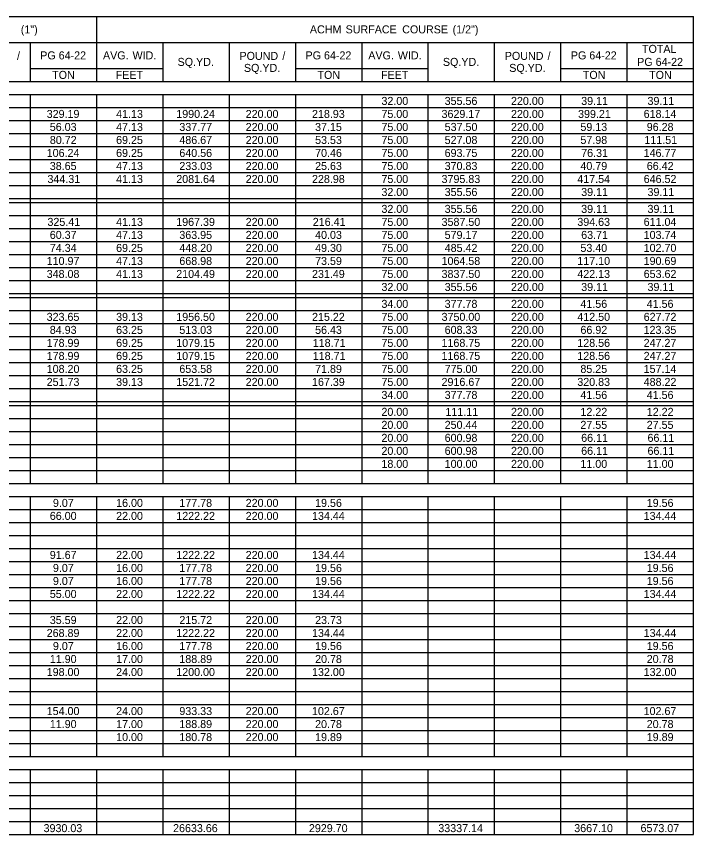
# Model space of a CAD drawing. Extents: x 977434 to 989596, y 1525697 to 1528336.
# Drawn here: x 983656.5 to 984062.7, y 1527610.4 to 1528101.1 of the extents above; entities that cross this region are included whole.
import ezdxf

# ---------------------------------------------------------------- set-up
doc = ezdxf.new("R2010")
doc.units = 0
doc.layers.add('Default', color=7, linetype='Continuous')

msp = doc.modelspace()

# ---------------------------------------------------------------- linework, layer by layer
at = {"layer": 'Default'}
for p, q in [((982704.74, 1528101.06), (984062.72, 1528101.06)), ((983704.7, 1528085.46), (983704.7, 1528101.06)), ((983704.7, 1528062.06), (983704.7, 1528101.06)), ((984062.72, 1527610.44), (984062.72, 1528101.06)), ((984062.72, 1527610.44), (984062.72, 1528101.06)), ((983028.44, 1528085.46), (984062.72, 1528085.46)), ((983664.92, 1528062.06), (983664.92, 1528085.46)), ((983744.48, 1528085.46), (983784.26, 1528085.46)), ((983744.48, 1528062.06), (983744.48, 1528085.46)), ((983784.26, 1528062.06), (983784.26, 1528085.46)), ((983824.04, 1528062.06), (983824.04, 1528085.46)), ((983863.82, 1528062.06), (983863.82, 1528085.46)), ((983903.6, 1528085.46), (983943.38, 1528085.46)), ((983903.6, 1528062.06), (983903.6, 1528085.46)), ((983943.38, 1528062.06), (983943.38, 1528085.46)), ((983983.16, 1528062.06), (983983.16, 1528085.46)), ((984022.94, 1528062.06), (984022.94, 1528085.46)), ((983664.92, 1528069.86), (983744.48, 1528069.86)), ((983704.7, 1528062.06), (983704.7, 1528069.86)), ((983744.48, 1528062.06), (983744.48, 1528069.86)), ((983824.04, 1528069.86), (983903.6, 1528069.86)), ((983863.82, 1528062.06), (983863.82, 1528069.86)), ((983903.6, 1528062.06), (983903.6, 1528069.86)), ((983983.16, 1528069.86), (984062.72, 1528069.86)), ((982704.74, 1528062.06), (984062.72, 1528062.06)), ((983585.36, 1528062.06), (983744.48, 1528062.06)), ((983744.48, 1528062.06), (983903.6, 1528062.06)), ((983903.6, 1528062.06), (984062.72, 1528062.06)), ((982704.74, 1528054.26), (984062.72, 1528054.26)), ((983664.92, 1527821.04), (983664.92, 1528054.26)), ((983664.92, 1527821.04), (983664.92, 1528054.26)), ((983704.7, 1527821.04), (983704.7, 1528054.26)), ((983704.7, 1527821.04), (983704.7, 1528054.26)), ((983744.48, 1527821.04), (983744.48, 1528054.26)), ((983744.48, 1527821.04), (983744.48, 1528054.26)), ((983784.26, 1527821.04), (983784.26, 1528054.26)), ((983784.26, 1527821.04), (983784.26, 1528054.26)), ((983824.04, 1527821.04), (983824.04, 1528054.26)), ((983824.04, 1527821.04), (983824.04, 1528054.26)), ((983863.82, 1527821.04), (983863.82, 1528054.26)), ((983863.82, 1527821.04), (983863.82, 1528054.26)), ((983903.6, 1527821.04), (983903.6, 1528054.26)), ((983903.6, 1527821.04), (983903.6, 1528054.26)), ((983943.38, 1527821.04), (983943.38, 1528054.26)), ((983943.38, 1527821.04), (983943.38, 1528054.26)), ((983983.16, 1527821.04), (983983.16, 1528054.26)), ((983983.16, 1527821.04), (983983.16, 1528054.26)), ((984022.94, 1527821.04), (984022.94, 1528054.26)), ((984022.94, 1527821.04), (984022.94, 1528054.26)), ((982704.74, 1528046.46), (984062.72, 1528046.46)), ((982704.74, 1528038.66), (984062.72, 1528038.66)), ((982704.74, 1528030.86), (984062.72, 1528030.86)), ((982704.74, 1528023.06), (984062.72, 1528023.06)), ((982704.74, 1528015.26), (984062.72, 1528015.26)), ((982704.74, 1528007.46), (984062.72, 1528007.46)), ((982704.74, 1527999.66), (984062.72, 1527999.66)), ((982704.74, 1527991.86), (984062.72, 1527991.86)), ((982704.74, 1527989.52), (984062.72, 1527989.52)), ((982704.74, 1527981.72), (984062.72, 1527981.72)), ((982704.74, 1527973.92), (984062.72, 1527973.92)), ((982704.74, 1527966.12), (984062.72, 1527966.12)), ((982704.74, 1527958.32), (984062.72, 1527958.32)), ((982704.74, 1527950.52), (984062.72, 1527950.52)), ((982704.74, 1527942.72), (984062.72, 1527942.72)), ((982704.74, 1527934.92), (984062.72, 1527934.92)), ((982704.74, 1527932.58), (984062.72, 1527932.58)), ((982704.74, 1527924.78), (984062.72, 1527924.78)), ((982704.74, 1527916.98), (984062.72, 1527916.98)), ((982704.74, 1527909.18), (984062.72, 1527909.18)), ((982704.74, 1527901.38), (984062.72, 1527901.38)), ((982704.74, 1527893.58), (984062.72, 1527893.58)), ((982704.74, 1527885.78), (984062.72, 1527885.78)), ((982704.74, 1527877.98), (984062.72, 1527877.98)), ((982704.74, 1527870.18), (984062.72, 1527870.18)), ((982704.74, 1527867.84), (984062.72, 1527867.84)), ((982704.74, 1527860.04), (984062.72, 1527860.04)), ((982704.74, 1527852.24), (984062.72, 1527852.24)), ((982704.74, 1527844.44), (984062.72, 1527844.44)), ((982704.74, 1527836.64), (984062.72, 1527836.64)), ((982704.74, 1527828.84), (984062.72, 1527828.84)), ((982704.74, 1527821.04), (984062.72, 1527821.04)), ((983386.46, 1527821.04), (983903.6, 1527821.04)), ((983903.6, 1527821.04), (983943.38, 1527821.04)), ((983943.38, 1527821.04), (984022.94, 1527821.04)), ((984022.94, 1527821.04), (984062.72, 1527821.04)), ((982704.74, 1527813.24), (984062.72, 1527813.24)), ((983664.92, 1527657.24), (983664.92, 1527813.24)), ((983664.92, 1527657.24), (983664.92, 1527813.24)), ((983704.7, 1527657.24), (983704.7, 1527813.24)), ((983704.7, 1527657.24), (983704.7, 1527813.24)), ((983744.48, 1527657.24), (983744.48, 1527813.24)), ((983744.48, 1527657.24), (983744.48, 1527813.24)), ((983784.26, 1527657.24), (983784.26, 1527813.24)), ((983784.26, 1527657.24), (983784.26, 1527813.24)), ((983824.04, 1527657.24), (983824.04, 1527813.24)), ((983824.04, 1527657.24), (983824.04, 1527813.24)), ((983863.82, 1527657.24), (983863.82, 1527813.24)), ((983863.82, 1527657.24), (983863.82, 1527813.24)), ((983903.6, 1527657.24), (983903.6, 1527813.24)), ((983903.6, 1527657.24), (983903.6, 1527813.24)), ((983943.38, 1527657.24), (983943.38, 1527813.24)), ((983943.38, 1527657.24), (983943.38, 1527813.24)), ((983983.16, 1527657.24), (983983.16, 1527813.24)), ((983983.16, 1527657.24), (983983.16, 1527813.24)), ((984022.94, 1527657.24), (984022.94, 1527813.24)), ((984022.94, 1527657.24), (984022.94, 1527813.24)), ((982704.74, 1527805.44), (984062.72, 1527805.44)), ((982704.74, 1527797.64), (984062.72, 1527797.64)), ((982704.74, 1527789.84), (984062.72, 1527789.84)), ((982704.74, 1527782.04), (984062.72, 1527782.04)), ((982704.74, 1527774.24), (984062.72, 1527774.24)), ((982704.74, 1527766.44), (984062.72, 1527766.44)), ((982704.74, 1527758.64), (984062.72, 1527758.64)), ((982704.74, 1527750.84), (984062.72, 1527750.84)), ((982704.74, 1527743.04), (984062.72, 1527743.04)), ((982704.74, 1527735.24), (984062.72, 1527735.24)), ((982704.74, 1527727.44), (984062.72, 1527727.44)), ((982704.74, 1527719.64), (984062.72, 1527719.64)), ((982704.74, 1527711.84), (984062.72, 1527711.84)), ((982704.74, 1527704.04), (984062.72, 1527704.04)), ((982704.74, 1527696.24), (984062.72, 1527696.24)), ((982704.74, 1527688.44), (984062.72, 1527688.44)), ((982704.74, 1527680.64), (984062.72, 1527680.64)), ((982704.74, 1527672.84), (984062.72, 1527672.84)), ((982704.74, 1527665.04), (984062.72, 1527665.04)), ((982704.74, 1527657.24), (984062.72, 1527657.24)), ((983346.68, 1527657.24), (983903.6, 1527657.24)), ((983903.6, 1527657.24), (983943.38, 1527657.24)), ((983943.38, 1527657.24), (984022.94, 1527657.24)), ((984022.94, 1527657.24), (984062.72, 1527657.24)), ((982704.74, 1527649.44), (984062.72, 1527649.44)), ((983664.92, 1527618.24), (983664.92, 1527649.44)), ((983664.92, 1527610.44), (983664.92, 1527649.44)), ((983704.7, 1527610.44), (983704.7, 1527649.44)), ((983704.7, 1527610.44), (983704.7, 1527649.44)), ((983744.48, 1527610.44), (983744.48, 1527649.44)), ((983744.48, 1527610.44), (983744.48, 1527649.44)), ((983784.26, 1527610.44), (983784.26, 1527649.44)), ((983784.26, 1527610.44), (983784.26, 1527649.44)), ((983824.04, 1527618.24), (983824.04, 1527649.44)), ((983824.04, 1527610.44), (983824.04, 1527649.44)), ((983863.82, 1527610.44), (983863.82, 1527649.44)), ((983863.82, 1527610.44), (983863.82, 1527649.44)), ((983903.6, 1527610.44), (983903.6, 1527649.44)), ((983903.6, 1527610.44), (983903.6, 1527649.44)), ((983943.38, 1527610.44), (983943.38, 1527649.44)), ((983943.38, 1527610.44), (983943.38, 1527649.44)), ((983983.16, 1527618.24), (983983.16, 1527649.44)), ((983983.16, 1527610.44), (983983.16, 1527649.44)), ((984022.94, 1527610.44), (984022.94, 1527649.44)), ((984022.94, 1527610.44), (984022.94, 1527649.44)), ((982704.74, 1527641.64), (984062.72, 1527641.64)), ((982704.74, 1527633.84), (984062.72, 1527633.84)), ((982704.74, 1527626.04), (984062.72, 1527626.04)), ((982704.74, 1527618.24), (984062.72, 1527618.24)), ((982704.74, 1527610.44), (984062.72, 1527610.44))]:
    msp.add_line(p, q, dxfattribs=at)

# ---------------------------------------------------------------- texts
for s, p in [(' (1")', (983657.4, 1528090.86)), ('ACHM', (983832.56, 1528090.86)), (' SURFACE', (983852.2, 1528090.86)), (' COURSE', (983886.15, 1528090.86)), (' (1/2")', (983916.38, 1528090.86)), ('TOTAL', (984031.75, 1528079.16)), (' /', (983655.11, 1528074.96)), ('PG', (983670.83, 1528075.26)), (' 64-22', (983680.12, 1528075.26)), ('AVG.', (983708.47, 1528075.26)), (' WID.', (983724.41, 1528075.26)), ('SQ.YD.', (983753.23, 1528071.36)), ('POUND', (983790.34, 1528074.96)), (' /', (983814.23, 1528074.96)), ('PG', (983829.95, 1528075.26)), (' 64-22', (983839.24, 1528075.26)), ('AVG.', (983867.59, 1528075.26)), (' WID.', (983883.53, 1528075.26)), ('SQ.YD.', (983912.35, 1528071.36)), ('POUND', (983949.46, 1528074.96)), (' /', (983973.35, 1528074.96)), ('PG', (983989.07, 1528075.26)), (' 64-22', (983998.36, 1528075.26)), ('PG', (984028.85, 1528071.36)), (' 64-22', (984038.14, 1528071.36)), ('SQ.YD.', (983793.01, 1528067.76)), ('SQ.YD.', (983952.13, 1528067.76)), ('TON', (983678, 1528063.56)), ('FEET', (983716.09, 1528063.56)), ('TON', (983837.12, 1528063.56)), ('FEET', (983875.21, 1528063.56)), ('TON', (983996.24, 1528063.56)), ('TON', (984036.02, 1528063.56)), ('32.00', (983875.48, 1528047.96)), ('355.56', (983913.39, 1528047.96)), ('220.00', (983953.18, 1528047.96)), ('39.11', (983995.28, 1528047.96)), ('39.11', (984035.06, 1528047.96)), ('329.19', (983674.71, 1528040.16)), ('41.13', (983716.35, 1528040.16)), ('1990.24', (983752.42, 1528040.16)), ('220.00', (983794.06, 1528040.16)), ('218.93', (983833.83, 1528040.16)), ('75.00', (983875.48, 1528040.16)), ('3629.17', (983911.53, 1528040.16)), ('220.00', (983953.18, 1528040.16)), ('399.21', (983993.41, 1528040.16)), ('618.14', (984032.74, 1528040.16)), ('56.03', (983676.57, 1528032.36)), ('47.13', (983716.35, 1528032.36)), ('337.77', (983754.27, 1528032.36)), ('220.00', (983794.06, 1528032.36)), ('37.15', (983835.68, 1528032.36)), ('75.00', (983875.48, 1528032.36)), ('537.50', (983913.4, 1528032.36)), ('220.00', (983953.18, 1528032.36)), ('59.13', (983994.81, 1528032.36)), ('96.28', (984034.59, 1528032.36)), ('80.72', (983676.6, 1528024.56)), ('69.25', (983716.34, 1528024.56)), ('486.67', (983754.27, 1528024.56)), ('220.00', (983794.06, 1528024.56)), ('53.53', (983835.69, 1528024.56)), ('75.00', (983875.48, 1528024.56)), ('527.08', (983913.39, 1528024.56)), ('220.00', (983953.18, 1528024.56)), ('57.98', (983994.81, 1528024.56)), ('111.51', (984033.19, 1528024.56)), ('106.24', (983674.72, 1528016.76)), ('69.25', (983716.34, 1528016.76)), ('640.56', (983754.27, 1528016.76)), ('220.00', (983794.06, 1528016.76)), ('70.46', (983835.69, 1528016.76)), ('75.00', (983875.48, 1528016.76)), ('693.75', (983913.37, 1528016.76)), ('220.00', (983953.18, 1528016.76)), ('76.31', (983995.28, 1528016.76)), ('146.77', (984032.73, 1528016.76)), ('38.65', (983676.56, 1528008.96)), ('47.13', (983716.35, 1528008.96)), ('233.03', (983754.27, 1528008.96)), ('220.00', (983794.06, 1528008.96)), ('25.63', (983835.69, 1528008.96)), ('75.00', (983875.48, 1528008.96)), ('370.83', (983913.39, 1528008.96)), ('220.00', (983953.18, 1528008.96)), ('40.79', (983994.81, 1528008.96)), ('66.42', (984034.62, 1528008.96)), ('344.31', (983675.17, 1528001.16)), ('41.13', (983716.35, 1528001.16)), ('2081.64', (983752.42, 1528001.16)), ('220.00', (983794.06, 1528001.16)), ('228.98', (983833.83, 1528001.16)), ('75.00', (983875.48, 1528001.16)), ('3795.83', (983911.53, 1528001.16)), ('220.00', (983953.18, 1528001.16)), ('417.54', (983992.96, 1528001.16)), ('646.52', (984032.76, 1528001.16)), ('32.00', (983875.48, 1527993.36)), ('355.56', (983913.39, 1527993.36)), ('220.00', (983953.18, 1527993.36)), ('39.11', (983995.28, 1527993.36)), ('39.11', (984035.06, 1527993.36)), ('32.00', (983875.48, 1527983.22)), ('355.56', (983913.39, 1527983.22)), ('220.00', (983953.18, 1527983.22)), ('39.11', (983995.28, 1527983.22)), ('39.11', (984035.06, 1527983.22)), ('325.41', (983675.17, 1527975.42)), ('41.13', (983716.35, 1527975.42)), ('1967.39', (983752.4, 1527975.42)), ('220.00', (983794.06, 1527975.42)), ('216.41', (983834.29, 1527975.42)), ('75.00', (983875.48, 1527975.42)), ('3587.50', (983911.54, 1527975.42)), ('220.00', (983953.18, 1527975.42)), ('394.63', (983992.95, 1527975.42)), ('611.04', (984032.74, 1527975.42)), ('60.37', (983676.57, 1527967.62)), ('47.13', (983716.35, 1527967.62)), ('363.95', (983754.25, 1527967.62)), ('220.00', (983794.06, 1527967.62)), ('40.03', (983835.69, 1527967.62)), ('75.00', (983875.48, 1527967.62)), ('579.17', (983913.39, 1527967.62)), ('220.00', (983953.18, 1527967.62)), ('63.71', (983995.28, 1527967.62)), ('103.74', (984032.74, 1527967.62)), ('74.34', (983676.59, 1527959.82)), ('69.25', (983716.34, 1527959.82)), ('448.20', (983754.28, 1527959.82)), ('220.00', (983794.06, 1527959.82)), ('49.30', (983835.7, 1527959.82)), ('75.00', (983875.48, 1527959.82)), ('485.42', (983913.42, 1527959.82)), ('220.00', (983953.18, 1527959.82)), ('53.40', (983994.82, 1527959.82)), ('102.70', (984032.74, 1527959.82)), ('110.97', (983674.71, 1527952.02)), ('47.13', (983716.35, 1527952.02)), ('668.98', (983754.27, 1527952.02)), ('220.00', (983794.06, 1527952.02)), ('73.59', (983835.69, 1527952.02)), ('75.00', (983875.48, 1527952.02)), ('1064.58', (983911.52, 1527952.02)), ('220.00', (983953.18, 1527952.02)), ('117.10', (983992.96, 1527952.02)), ('190.69', (984032.73, 1527952.02)), ('348.08', (983674.71, 1527944.22)), ('41.13', (983716.35, 1527944.22)), ('2104.49', (983752.4, 1527944.22)), ('220.00', (983794.06, 1527944.22)), ('231.49', (983833.83, 1527944.22)), ('75.00', (983875.48, 1527944.22)), ('3837.50', (983911.54, 1527944.22)), ('220.00', (983953.18, 1527944.22)), ('422.13', (983992.95, 1527944.22)), ('653.62', (984032.76, 1527944.22)), ('32.00', (983875.48, 1527936.42)), ('355.56', (983913.39, 1527936.42)), ('220.00', (983953.18, 1527936.42)), ('39.11', (983995.28, 1527936.42)), ('39.11', (984035.06, 1527936.42)), ('34.00', (983875.48, 1527926.28)), ('377.78', (983913.39, 1527926.28)), ('220.00', (983953.18, 1527926.28)), ('41.56', (983994.81, 1527926.28)), ('41.56', (984034.59, 1527926.28)), ('323.65', (983674.69, 1527918.48)), ('39.13', (983716.35, 1527918.48)), ('1956.50', (983752.42, 1527918.48)), ('220.00', (983794.06, 1527918.48)), ('215.22', (983833.86, 1527918.48)), ('75.00', (983875.48, 1527918.48)), ('3750.00', (983911.54, 1527918.48)), ('220.00', (983953.18, 1527918.48)), ('412.50', (983992.96, 1527918.48)), ('627.72', (984032.76, 1527918.48)), ('84.93', (983676.57, 1527910.68)), ('63.25', (983716.34, 1527910.68)), ('513.03', (983754.27, 1527910.68)), ('220.00', (983794.06, 1527910.68)), ('56.43', (983835.69, 1527910.68)), ('75.00', (983875.48, 1527910.68)), ('608.33', (983913.39, 1527910.68)), ('220.00', (983953.18, 1527910.68)), ('66.92', (983994.84, 1527910.68)), ('123.35', (984032.71, 1527910.68)), ('178.99', (983674.71, 1527902.88)), ('69.25', (983716.34, 1527902.88)), ('1079.15', (983752.39, 1527902.88)), ('220.00', (983794.06, 1527902.88)), ('118.71', (983834.29, 1527902.88)), ('75.00', (983875.48, 1527902.88)), ('1168.75', (983911.51, 1527902.88)), ('220.00', (983953.18, 1527902.88)), ('128.56', (983992.95, 1527902.88)), ('247.27', (984032.73, 1527902.88)), ('178.99', (983674.71, 1527895.08)), ('69.25', (983716.34, 1527895.08)), ('1079.15', (983752.39, 1527895.08)), ('220.00', (983794.06, 1527895.08)), ('118.71', (983834.29, 1527895.08)), ('75.00', (983875.48, 1527895.08)), ('1168.75', (983911.51, 1527895.08)), ('220.00', (983953.18, 1527895.08)), ('128.56', (983992.95, 1527895.08)), ('247.27', (984032.73, 1527895.08)), ('108.20', (983674.72, 1527887.28)), ('63.25', (983716.34, 1527887.28)), ('653.58', (983754.27, 1527887.28)), ('220.00', (983794.06, 1527887.28)), ('71.89', (983835.69, 1527887.28)), ('75.00', (983875.48, 1527887.28)), ('775.00', (983913.4, 1527887.28)), ('220.00', (983953.18, 1527887.28)), ('85.25', (983994.8, 1527887.28)), ('157.14', (984032.74, 1527887.28)), ('251.73', (983674.71, 1527879.48)), ('39.13', (983716.35, 1527879.48)), ('1521.72', (983752.43, 1527879.48)), ('220.00', (983794.06, 1527879.48)), ('167.39', (983833.83, 1527879.48)), ('75.00', (983875.48, 1527879.48)), ('2916.67', (983911.53, 1527879.48)), ('220.00', (983953.18, 1527879.48)), ('320.83', (983992.95, 1527879.48)), ('488.22', (984032.76, 1527879.48)), ('34.00', (983875.48, 1527871.68)), ('377.78', (983913.39, 1527871.68)), ('220.00', (983953.18, 1527871.68)), ('41.56', (983994.81, 1527871.68)), ('41.56', (984034.59, 1527871.68)), ('20.00', (983875.48, 1527861.54)), ('111.11', (983913.85, 1527861.54)), ('220.00', (983953.18, 1527861.54)), ('12.22', (983994.84, 1527861.54)), ('12.22', (984034.62, 1527861.54)), ('20.00', (983875.48, 1527853.74)), ('250.44', (983913.4, 1527853.74)), ('220.00', (983953.18, 1527853.74)), ('27.55', (983994.8, 1527853.74)), ('27.55', (984034.58, 1527853.74)), ('20.00', (983875.48, 1527845.94)), ('600.98', (983913.39, 1527845.94)), ('220.00', (983953.18, 1527845.94)), ('66.11', (983995.28, 1527845.94)), ('66.11', (984035.06, 1527845.94)), ('20.00', (983875.48, 1527838.14)), ('600.98', (983913.39, 1527838.14)), ('220.00', (983953.18, 1527838.14)), ('66.11', (983995.28, 1527838.14)), ('66.11', (984035.06, 1527838.14)), ('18.00', (983875.48, 1527830.34)), ('100.00', (983913.4, 1527830.34)), ('220.00', (983953.18, 1527830.34)), ('11.00', (983994.82, 1527830.34)), ('11.00', (984034.6, 1527830.34)), ('9.07', (983678.44, 1527806.94)), ('16.00', (983716.36, 1527806.94)), ('177.78', (983754.27, 1527806.94)), ('220.00', (983794.06, 1527806.94)), ('19.56', (983835.69, 1527806.94)), ('19.56', (984034.59, 1527806.94)), ('66.00', (983676.58, 1527799.14)), ('22.00', (983716.36, 1527799.14)), ('1222.22', (983752.43, 1527799.14)), ('220.00', (983794.06, 1527799.14)), ('134.44', (983833.84, 1527799.14)), ('134.44', (984032.74, 1527799.14)), ('91.67', (983676.57, 1527775.74)), ('22.00', (983716.36, 1527775.74)), ('1222.22', (983752.43, 1527775.74)), ('220.00', (983794.06, 1527775.74)), ('134.44', (983833.84, 1527775.74)), ('134.44', (984032.74, 1527775.74)), ('9.07', (983678.44, 1527767.94)), ('16.00', (983716.36, 1527767.94)), ('177.78', (983754.27, 1527767.94)), ('220.00', (983794.06, 1527767.94)), ('19.56', (983835.69, 1527767.94)), ('19.56', (984034.59, 1527767.94)), ('9.07', (983678.44, 1527760.14)), ('16.00', (983716.36, 1527760.14)), ('177.78', (983754.27, 1527760.14)), ('220.00', (983794.06, 1527760.14)), ('19.56', (983835.69, 1527760.14)), ('19.56', (984034.59, 1527760.14)), ('55.00', (983676.58, 1527752.34)), ('22.00', (983716.36, 1527752.34)), ('1222.22', (983752.43, 1527752.34)), ('220.00', (983794.06, 1527752.34)), ('134.44', (983833.84, 1527752.34)), ('134.44', (984032.74, 1527752.34)), ('35.59', (983676.57, 1527736.74)), ('22.00', (983716.36, 1527736.74)), ('215.72', (983754.3, 1527736.74)), ('220.00', (983794.06, 1527736.74)), ('23.73', (983835.69, 1527736.74)), ('268.89', (983674.71, 1527728.94)), ('22.00', (983716.36, 1527728.94)), ('1222.22', (983752.43, 1527728.94)), ('220.00', (983794.06, 1527728.94)), ('134.44', (983833.84, 1527728.94)), ('134.44', (984032.74, 1527728.94)), ('9.07', (983678.44, 1527721.14)), ('16.00', (983716.36, 1527721.14)), ('177.78', (983754.27, 1527721.14)), ('220.00', (983794.06, 1527721.14)), ('19.56', (983835.69, 1527721.14)), ('19.56', (984034.59, 1527721.14)), ('11.90', (983676.58, 1527713.34)), ('17.00', (983716.36, 1527713.34)), ('188.89', (983754.27, 1527713.34)), ('220.00', (983794.06, 1527713.34)), ('20.78', (983835.69, 1527713.34)), ('20.78', (984034.59, 1527713.34)), ('198.00', (983674.72, 1527705.54)), ('24.00', (983716.36, 1527705.54)), ('1200.00', (983752.42, 1527705.54)), ('220.00', (983794.06, 1527705.54)), ('132.00', (983833.84, 1527705.54)), ('132.00', (984032.74, 1527705.54)), ('154.00', (983674.72, 1527682.14)), ('24.00', (983716.36, 1527682.14)), ('933.33', (983754.27, 1527682.14)), ('220.00', (983794.06, 1527682.14)), ('102.67', (983833.83, 1527682.14)), ('102.67', (984032.73, 1527682.14)), ('11.90', (983676.58, 1527674.34)), ('17.00', (983716.36, 1527674.34)), ('188.89', (983754.27, 1527674.34)), ('220.00', (983794.06, 1527674.34)), ('20.78', (983835.69, 1527674.34)), ('20.78', (984034.59, 1527674.34)), ('10.00', (983716.36, 1527666.54)), ('180.78', (983754.27, 1527666.54)), ('220.00', (983794.06, 1527666.54)), ('19.89', (983835.69, 1527666.54)), ('19.89', (984034.59, 1527666.54)), ('3930.03', (983672.84, 1527611.94)), ('26633.66', (983750.51, 1527611.94)), ('2929.70', (983831.98, 1527611.94)), ('33337.14', (983909.59, 1527611.94)), ('3667.10', (983991.1, 1527611.94)), ('6573.07', (984030.86, 1527611.94))]:
    msp.add_text(s, height=4.8, dxfattribs=at).set_placement(p)

doc.saveas('drawing.dxf')
